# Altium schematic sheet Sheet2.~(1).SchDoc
size A4; SheetNumber: 2; SheetTotal: 2
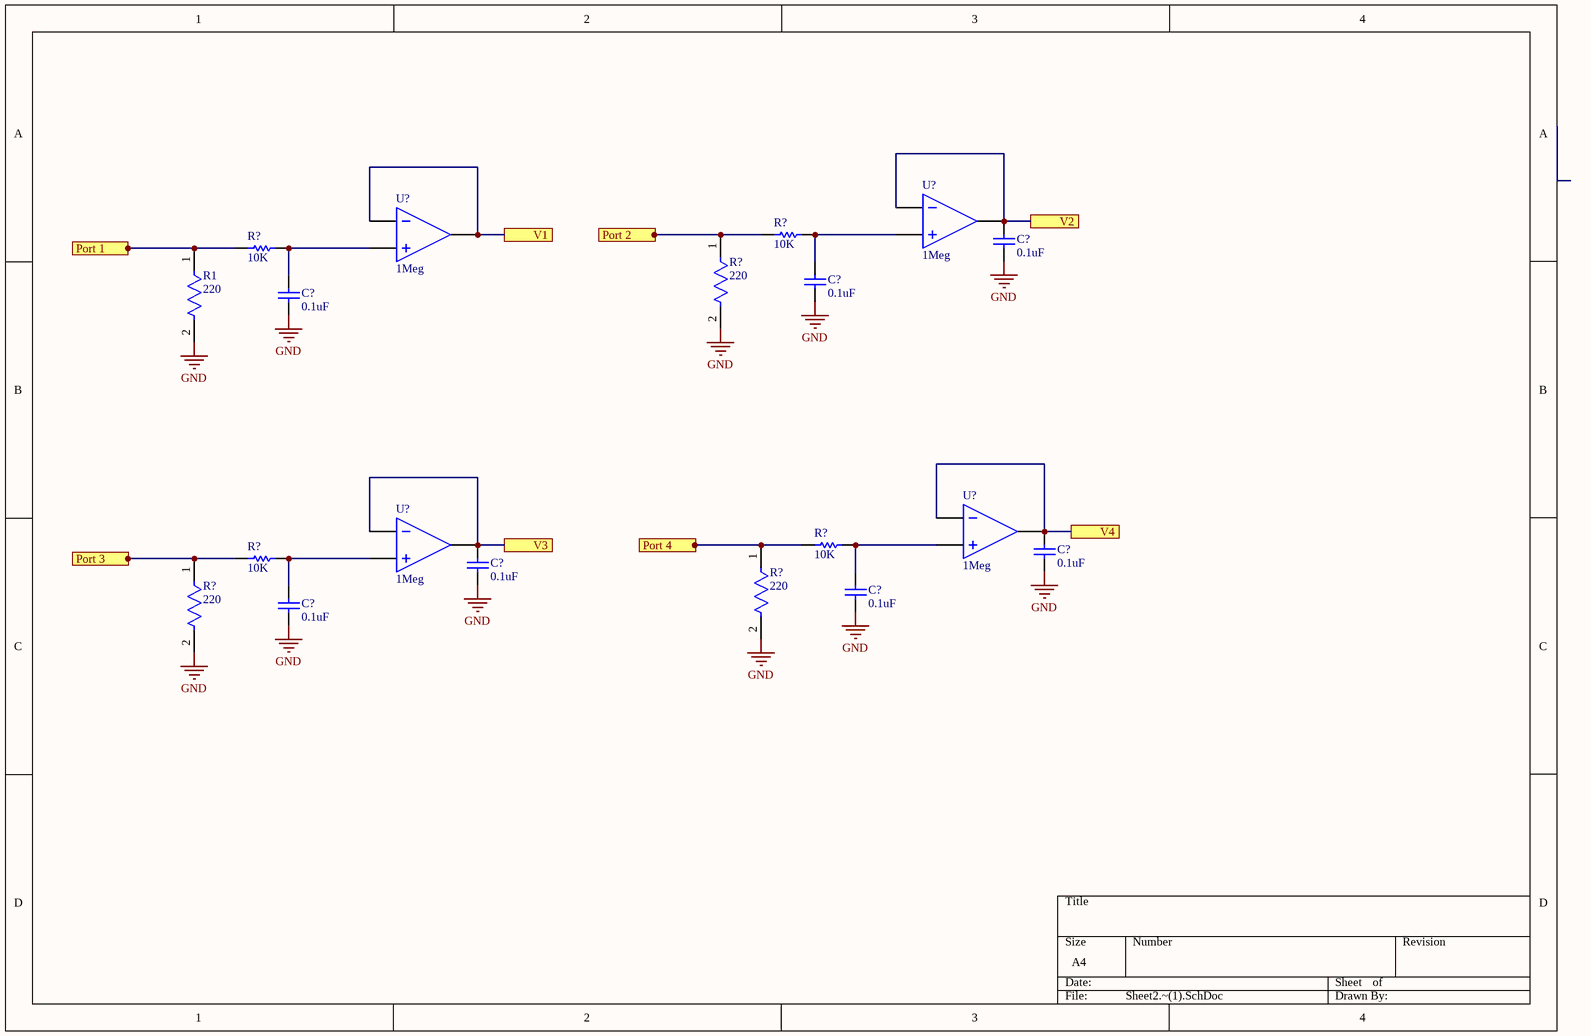
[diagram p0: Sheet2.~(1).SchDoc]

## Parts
(Parts that share a designator on the sheet are numbered #1, #2 ... from top to bottom, then left to right.)
C?#1  value 0.1uF  (hidden comment: Capacitor)
C?#2  value 0.1uF  (hidden comment: Capacitor)
C?#3  value 0.1uF  (hidden comment: Capacitor)
C?#4  value 0.1uF  (hidden comment: Capacitor)
C?#5  value 0.1uF  (hidden comment: Capacitor)
C?#6  value 0.1uF  (hidden comment: Capacitor)
C?#7  value 0.1uF  (hidden comment: Capacitor)
R1  220  [FP-CRCW0603-e3-MFG]
R?#1  220  [FP-CRCW0603-e3-MFG]
R?#2  value 10K  (hidden comment: Resistor)
R?#3  value 10K  (hidden comment: Resistor)
R?#4  220  [FP-CRCW0603-e3-MFG]
R?#5  value 10K  (hidden comment: Resistor)
R?#6  220  [FP-CRCW0603-e3-MFG]
R?#7  value 10K  (hidden comment: Resistor)
U?#1  GAIN: 1Meg  (hidden comment: Ideal Operational Amplifier)
U?#2  GAIN: 1Meg  (hidden comment: Ideal Operational Amplifier)
U?#3  GAIN: 1Meg  (hidden comment: Ideal Operational Amplifier)
U?#4  GAIN: 1Meg  (hidden comment: Ideal Operational Amplifier)

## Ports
Port 1, Port 2, Port 3, Port 4, V1, V2, V3, V4

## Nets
GND: C?#1.1 C?#2.1 C?#3.1 C?#4.1 C?#5.1 C?#6.1 C?#7.1 R1.2 R?#1.2 R?#4.2 R?#6.2
Port 1: R1.1 R?#3.1 ; port Port 1
Port 2: R?#1.1 R?#2.1 ; port Port 2
Port 3: R?#6.1 R?#7.1 ; port Port 3
Port 4: R?#4.1 R?#5.1 ; port Port 4
V1: U?#2.1(IN-) U?#2.3(OUT) ; port V1
V2: C?#1.2 U?#1.1(IN-) U?#1.3(OUT) ; port V2
V3: C?#5.2 U?#4.1(IN-) U?#4.3(OUT) ; port V3
V4: C?#4.2 U?#3.1(IN-) U?#3.3(OUT) ; port V4
NetC?#2_2: C?#2.2 R?#2.2 U?#1.2(IN+)
NetC?#3_2: C?#3.2 R?#3.2 U?#2.2(IN+)
NetC?#6_2: C?#6.2 R?#5.2 U?#3.2(IN+)
NetC?#7_2: C?#7.2 R?#7.2 U?#4.2(IN+)

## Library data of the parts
C?#1-C?#7 = Capacitor: SimulationGenericComponent: True
R1 R?#1 R?#4 R?#6 = CMP-2000-03085-2: RES Thick Film, 220Ω, 1%, 0.1W, 100ppm/°C, 0603; Power Rating: 100mW; Voltage Rating: 75V; Resistance: 220R
R?#2 R?#3 R?#5 R?#7 = Resistor: TC1: 0; SimulationGenericComponent: True
U?#1-U?#4 = OpAmp: SimulationGenericComponent: True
